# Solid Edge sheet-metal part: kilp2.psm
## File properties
Author: Kasutaja
Template: Iso Metric Sheet Metal.psm
Last saved by: Kasutaja
Revision: 4
Application: Solid Edge
Accuracy: 0,990
Material Thickness: 2,00 mm
Bend Radius: 1,00 mm
Relief Width: 1,00 mm
Relief Length: 0,00 mm
Neutral Factor: 0,330
Minimum Arc Length: 0,10 mm
Deviational Tolerance: 0,10 mm
Username: Kasutaja
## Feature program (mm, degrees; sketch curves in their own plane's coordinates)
base tab "unnamed BaseTab 1"
flange "Flange_1"
flange "Flange_2"
flange "Flange_3"
flange "Flange_4"
flange "Flange_5"
flange "Flange_6"
dimple "Dimple_1"
bead "Bead_1"
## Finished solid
Body 1: solid body, 86 faces, 168 edges, 84 vertices.
  Faces by surface: plane 50, cylinder 14, spline 12, torus 6, cone 4
  Edges by curve: line 114, circle 30, curve on surface 24
Bounding box of the edges (mm; curved faces can reach further): 72.568 x 12.000 x 64.041, from (-36.284, -7, -32.0205) to (36.284, 5, 32.0205).
Cylindrical faces by radius (mm): R1 x6, R3 x6, R5.5 x1, R7.5 x1
Conical faces (half-angle, radius in mm at the cone's reference point): 15 deg R15.9605 x1, 15 deg R17.8924 x1, 15 deg R21.1028 x1, 15 deg R23.0347 x1
Toroidal faces (ring radius, tube radius in mm): R5.5 r2 x1, R7.5 r2 x1, R15.9605 r2 x1, R18.5 r2 x1, R21.5 r2 x1, R24.0395 r2 x1
Planar faces by outward normal: +y 10, -y 10, oblique 30
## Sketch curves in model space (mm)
line (3.7422, 0, 6.4997) -> (9.9793, 0, 17.3324)
line (-3.7422, 0, -6.4997) -> (-9.9793, 0, -17.3324)
line (-6.4997, 0, 3.7422) -> (-17.3324, 0, 9.9793)
line (6.4997, 0, -3.7422) -> (17.3324, 0, -9.9793)
circle centre (0, 0, 0) radius 20
circle centre (0, 0, 0) radius 7.5
circle centre (0, 0, 0) radius 30
line (-17.2846, 0, -30.0207) -> (17.3564, 0, -29.9793)
line (17.3564, 0, -29.9793) -> (34.641, 0, 0.0414)
line (34.641, 0, 0.0414) -> (17.2846, 0, 30.0207)
line (17.2846, 0, 30.0207) -> (-17.3564, 0, 29.9793)
line (-17.3564, 0, 29.9793) -> (-34.641, 0, -0.0414)
line (-34.641, 0, -0.0414) -> (-17.2846, 0, -30.0207)
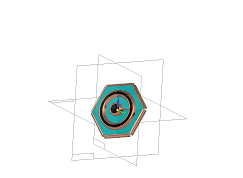
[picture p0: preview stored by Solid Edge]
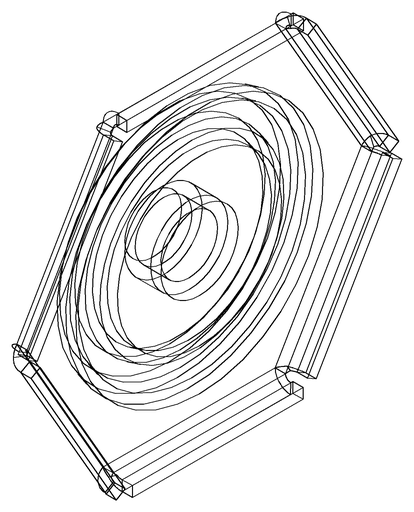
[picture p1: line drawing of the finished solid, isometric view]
